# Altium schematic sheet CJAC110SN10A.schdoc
size 127 x 101 mm
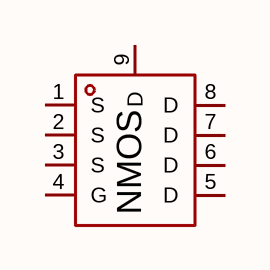
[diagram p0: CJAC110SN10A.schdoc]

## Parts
Q?  cjac110sn10a  [PDFN-8_L5.8-W4.9-P1.27-LS6.1-BL-A]  (value not drawn)

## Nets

Not connected (* = marked no-connect by the designer): Q? 1(S) 2(S) 3(S) 4(G) 5(D) 6(D) 7(D) 8(D) 9(D)

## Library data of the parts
Q? = cjac110sn10a: 数量:1个N沟道;漏源电压(Vdss):100V;连续漏极电流(Id):110A;导通电阻(RDS(on)):4.2mΩ@10V;耗散功率(Pd):125W;阈值电压(Vgs(th)):2.4V;; Manufacturer: CJ(江苏长电/长晶); AddInBom: yes; ModelId: 450a83d8ea544a1683b51becadb75d8a; ModelTransform: 200.787,238.189,0,0,0,0,-0.005,0.003,0; Number: 1个N沟道; Drain to Source Voltage: 100V; Current - Continuous Drain(Id): 110A; Pd - Power Dissipation: 125W; Gate Threshold Voltage (Vgs(th)): 2.4V; Gate Charge(Qg): 186nC@10V; Input Capacitance(Ciss): 7.47nF; Reverse Transfer Capacitance (Crss@Vds): 70pF; Type: N沟道; Output Capacitance(Coss): 1.8nF; Vgs: ±20V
